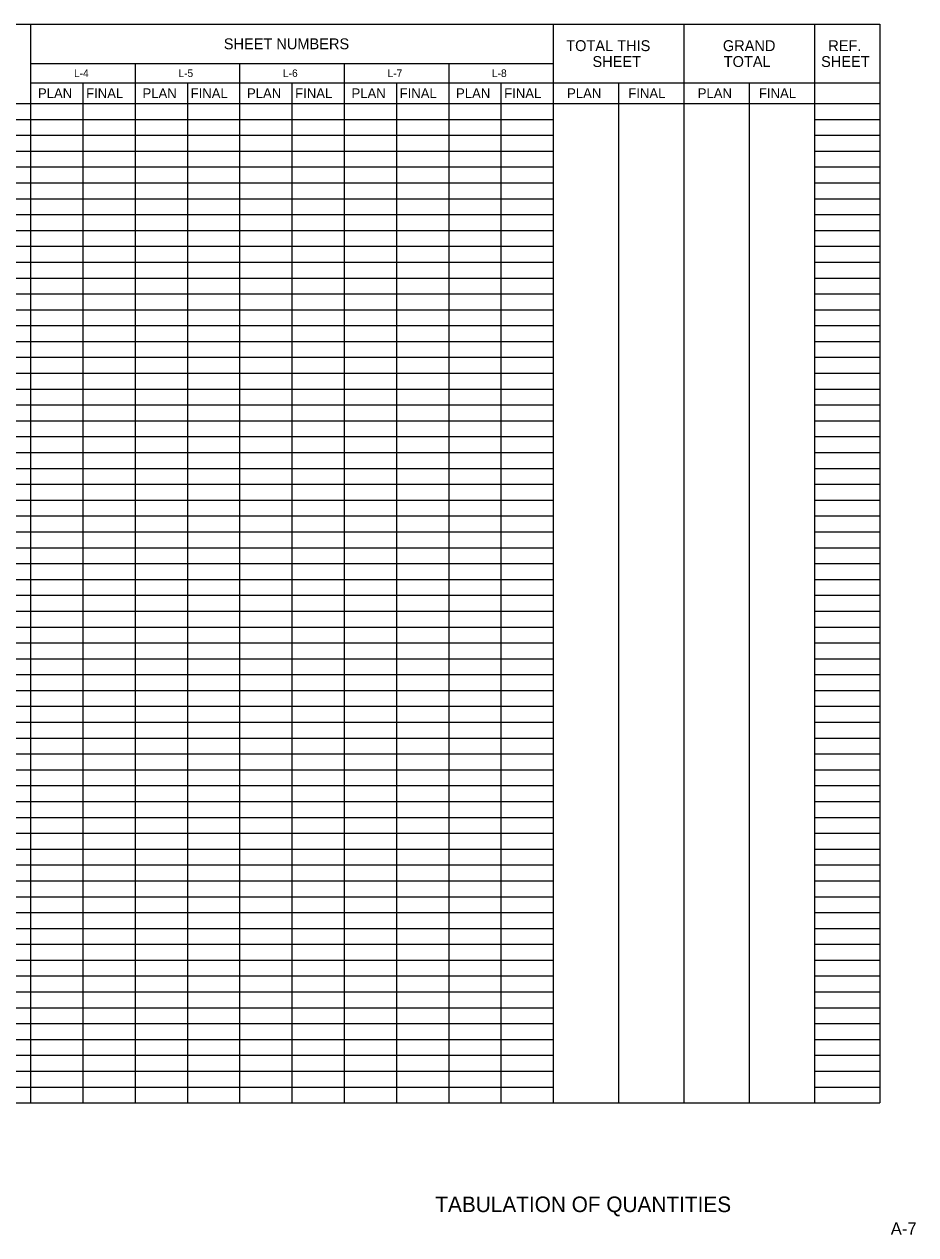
# Model space of a CAD drawing. Extents: x 56 to 1513, y -69 to 5602.
# Drawn here: x 796 to 1513, y 3444 to 4417 of the extents above; entities that cross this region are included whole.
import ezdxf

# ---------------------------------------------------------------- set-up
doc = ezdxf.new("R2010")
doc.units = 0
for name, color, linetype in [('Logo_dp', 7, 'Continuous'), ('SheetLines_dp', 7, 'Continuous'), ('TextCurveData', 7, 'Continuous'), ('TextMinor', 7, 'Continuous'), ('TextMisc', 7, 'Continuous'), ('TextNotes', 7, 'Continuous')]:
    doc.layers.add(name, color=color, linetype=linetype)

msp = doc.modelspace()

# ---------------------------------------------------------------- linework, layer by layer
at = {"layer": 'SheetLines_dp'}
for p, q in [((801.5, 4416.62), (801.5, 4369.37)), ((801.5, 4416.62), (801.5, 3549.62)), ((1221.5, 4416.62), (1221.5, 3549.62)), ((1221.5, 4416.62), (1221.5, 3549.62)), ((1326.5, 4416.62), (1326.5, 3549.62)), ((1431.5, 4416.62), (1431.5, 3549.62)), ((1484, 4416.62), (1484, 3549.62)), ((801.5, 4385.12), (1221.5, 4385.12)), ((801.5, 4385.12), (1221.5, 4385.12)), ((885.5, 4385.12), (885.5, 3549.62)), ((885.5, 4385.12), (885.5, 3549.62)), ((969.5, 4385.12), (969.5, 3549.62)), ((969.5, 4385.12), (969.5, 4369.37)), ((1053.5, 4385.12), (1053.5, 3549.62)), ((1053.5, 4385.12), (1053.5, 4369.37)), ((1137.5, 4385.12), (1137.5, 3549.62)), ((1137.5, 4385.12), (1137.5, 3549.62)), ((801.5, 4369.37), (1484, 4369.37)), ((1221.5, 4369.37), (1484, 4369.37)), ((1326.5, 4369.37), (1326.5, 3549.62)), ((56, 4352.87), (1484, 4352.87)), ((801.5, 4352.87), (801.5, 3549.62)), ((969.5, 4352.87), (969.5, 3549.62)), ((1053.5, 4352.87), (1053.5, 3549.62)), ((1221.5, 4352.87), (1431.5, 4352.87)), ((1431.5, 4352.87), (1431.5, 3549.62)), ((56, 3549.62), (1484, 3549.62))]:
    msp.add_line(p, q, dxfattribs=at)
at = {"layer": 'TextMinor'}
for q in [(1431.5, 4416.62), (1484, 4416.62)]:
    msp.add_line((56, 4416.62), q, dxfattribs=at)
at = {"layer": 'TextMisc'}
for p, q in [((843.5, 4369.37), (843.5, 3549.62)), ((843.5, 4369.37), (843.5, 3549.62)), ((927.5, 4369.37), (927.5, 3549.62)), ((927.5, 4369.37), (927.5, 3549.62)), ((969.5, 4369.37), (969.5, 4352.87)), ((1011.5, 4369.37), (1011.5, 3549.62)), ((1011.5, 4369.37), (1011.5, 3549.62)), ((1053.5, 4369.37), (1053.5, 4352.87)), ((1095.5, 4369.37), (1095.5, 3549.62)), ((1095.5, 4369.37), (1095.5, 3549.62)), ((1179.5, 4369.37), (1179.5, 3549.62)), ((1179.5, 4369.37), (1179.5, 3549.62)), ((1274, 4369.37), (1274, 3549.62)), ((1274, 4369.37), (1274, 3549.62)), ((1379, 4369.37), (1379, 3549.62)), ((1379, 4369.37), (1379, 3549.62)), ((56, 4352.87), (1221.5, 4352.87)), ((1431.5, 4352.87), (1484, 4352.87)), ((56, 4340.12), (1221.5, 4340.12)), ((56, 4340.12), (1221.5, 4340.12)), ((1431.5, 4340.12), (1484, 4340.12)), ((1431.5, 4340.12), (1484, 4340.12)), ((56, 4327.37), (1221.5, 4327.37)), ((56, 4327.37), (1221.5, 4327.37)), ((1431.5, 4327.37), (1484, 4327.37)), ((1431.5, 4327.37), (1484, 4327.37)), ((56, 4314.62), (1221.5, 4314.62)), ((56, 4314.62), (1221.5, 4314.62)), ((1431.5, 4314.62), (1484, 4314.62)), ((1431.5, 4314.62), (1484, 4314.62)), ((56, 4301.87), (1221.5, 4301.87)), ((56, 4301.87), (1221.5, 4301.87)), ((1431.5, 4301.87), (1484, 4301.87)), ((1431.5, 4301.87), (1484, 4301.87)), ((56, 4289.12), (1221.5, 4289.12)), ((56, 4289.12), (1221.5, 4289.12)), ((1431.5, 4289.12), (1484, 4289.12)), ((1431.5, 4289.12), (1484, 4289.12)), ((56, 4276.37), (1221.5, 4276.37)), ((56, 4276.37), (1221.5, 4276.37)), ((1431.5, 4276.37), (1484, 4276.37)), ((1431.5, 4276.37), (1484, 4276.37)), ((56, 4263.62), (1221.5, 4263.62)), ((56, 4263.62), (1221.5, 4263.62)), ((1431.5, 4263.62), (1484, 4263.62)), ((1431.5, 4263.62), (1484, 4263.62)), ((56, 4250.87), (1221.5, 4250.87)), ((56, 4250.87), (1221.5, 4250.87)), ((1431.5, 4250.87), (1484, 4250.87)), ((1431.5, 4250.87), (1484, 4250.87)), ((56, 4238.12), (1221.5, 4238.12)), ((56, 4238.12), (1221.5, 4238.12)), ((1431.5, 4238.12), (1484, 4238.12)), ((1431.5, 4238.12), (1484, 4238.12)), ((56, 4225.37), (1221.5, 4225.37)), ((56, 4225.37), (1221.5, 4225.37)), ((1431.5, 4225.37), (1484, 4225.37)), ((1431.5, 4225.37), (1484, 4225.37)), ((56, 4212.62), (1221.5, 4212.62)), ((56, 4212.62), (1221.5, 4212.62)), ((1431.5, 4212.62), (1484, 4212.62)), ((1431.5, 4212.62), (1484, 4212.62)), ((56, 4199.87), (1221.5, 4199.87)), ((56, 4199.87), (1221.5, 4199.87)), ((1431.5, 4199.87), (1484, 4199.87)), ((1431.5, 4199.87), (1484, 4199.87)), ((56, 4187.12), (1221.5, 4187.12)), ((56, 4187.12), (1221.5, 4187.12)), ((1431.5, 4187.12), (1484, 4187.12)), ((1431.5, 4187.12), (1484, 4187.12)), ((56, 4174.37), (1221.5, 4174.37)), ((56, 4174.37), (1221.5, 4174.37)), ((1431.5, 4174.37), (1484, 4174.37)), ((1431.5, 4174.37), (1484, 4174.37)), ((56, 4161.62), (1221.5, 4161.62)), ((56, 4161.62), (1221.5, 4161.62)), ((1431.5, 4161.62), (1484, 4161.62)), ((1431.5, 4161.62), (1484, 4161.62)), ((56, 4148.87), (1221.5, 4148.87)), ((56, 4148.87), (1221.5, 4148.87)), ((1431.5, 4148.87), (1484, 4148.87)), ((1431.5, 4148.87), (1484, 4148.87)), ((56, 4136.12), (1221.5, 4136.12)), ((56, 4136.12), (1221.5, 4136.12)), ((1431.5, 4136.12), (1484, 4136.12)), ((1431.5, 4136.12), (1484, 4136.12)), ((56, 4123.37), (1221.5, 4123.37)), ((56, 4123.37), (1221.5, 4123.37)), ((1431.5, 4123.37), (1484, 4123.37)), ((1431.5, 4123.37), (1484, 4123.37)), ((56, 4110.62), (1221.5, 4110.62)), ((56, 4110.62), (1221.5, 4110.62)), ((1431.5, 4110.62), (1484, 4110.62)), ((1431.5, 4110.62), (1484, 4110.62)), ((56, 4097.87), (1221.5, 4097.87)), ((56, 4097.87), (1221.5, 4097.87)), ((1431.5, 4097.87), (1484, 4097.87)), ((1431.5, 4097.87), (1484, 4097.87)), ((56, 4085.12), (1221.5, 4085.12)), ((56, 4085.12), (1221.5, 4085.12)), ((1431.5, 4085.12), (1484, 4085.12)), ((1431.5, 4085.12), (1484, 4085.12)), ((56, 4072.37), (1221.5, 4072.37)), ((56, 4072.37), (1221.5, 4072.37)), ((1431.5, 4072.37), (1484, 4072.37)), ((1431.5, 4072.37), (1484, 4072.37)), ((56, 4059.62), (1221.5, 4059.62)), ((56, 4059.62), (1221.5, 4059.62)), ((1431.5, 4059.62), (1484, 4059.62)), ((1431.5, 4059.62), (1484, 4059.62)), ((56, 4046.87), (1221.5, 4046.87)), ((56, 4046.87), (1221.5, 4046.87)), ((1431.5, 4046.87), (1484, 4046.87)), ((1431.5, 4046.87), (1484, 4046.87)), ((56, 4034.12), (1221.5, 4034.12)), ((56, 4034.12), (1221.5, 4034.12)), ((1431.5, 4034.12), (1484, 4034.12)), ((1431.5, 4034.12), (1484, 4034.12)), ((56, 4021.37), (1221.5, 4021.37)), ((56, 4021.37), (1221.5, 4021.37)), ((1431.5, 4021.37), (1484, 4021.37)), ((1431.5, 4021.37), (1484, 4021.37)), ((56, 4008.62), (1221.5, 4008.62)), ((56, 4008.62), (1221.5, 4008.62)), ((1431.5, 4008.62), (1484, 4008.62)), ((1431.5, 4008.62), (1484, 4008.62)), ((56, 3995.87), (1221.5, 3995.87)), ((56, 3995.87), (1221.5, 3995.87)), ((1431.5, 3995.87), (1484, 3995.87)), ((1431.5, 3995.87), (1484, 3995.87)), ((56, 3983.12), (1221.5, 3983.12)), ((56, 3983.12), (1221.5, 3983.12)), ((1431.5, 3983.12), (1484, 3983.12)), ((1431.5, 3983.12), (1484, 3983.12)), ((56, 3970.37), (1221.5, 3970.37)), ((56, 3970.37), (1221.5, 3970.37)), ((1431.5, 3970.37), (1484, 3970.37)), ((1431.5, 3970.37), (1484, 3970.37)), ((56, 3957.62), (1221.5, 3957.62)), ((56, 3957.62), (1221.5, 3957.62)), ((1431.5, 3957.62), (1484, 3957.62)), ((1431.5, 3957.62), (1484, 3957.62)), ((56, 3944.87), (1221.5, 3944.87)), ((56, 3944.87), (1221.5, 3944.87)), ((1431.5, 3944.87), (1484, 3944.87)), ((1431.5, 3944.87), (1484, 3944.87)), ((56, 3932.12), (1221.5, 3932.12)), ((56, 3932.12), (1221.5, 3932.12)), ((1431.5, 3932.12), (1484, 3932.12)), ((1431.5, 3932.12), (1484, 3932.12)), ((56, 3919.37), (1221.5, 3919.37)), ((56, 3919.37), (1221.5, 3919.37)), ((1431.5, 3919.37), (1484, 3919.37)), ((1431.5, 3919.37), (1484, 3919.37)), ((56, 3906.62), (1221.5, 3906.62)), ((56, 3906.62), (1221.5, 3906.62)), ((1431.5, 3906.62), (1484, 3906.62)), ((1431.5, 3906.62), (1484, 3906.62)), ((56, 3893.87), (1221.5, 3893.87)), ((56, 3893.87), (1221.5, 3893.87)), ((1431.5, 3893.87), (1484, 3893.87)), ((1431.5, 3893.87), (1484, 3893.87)), ((56, 3881.12), (1221.5, 3881.12)), ((56, 3881.12), (1221.5, 3881.12)), ((1431.5, 3881.12), (1484, 3881.12)), ((1431.5, 3881.12), (1484, 3881.12)), ((56, 3868.37), (1221.5, 3868.37)), ((56, 3868.37), (1221.5, 3868.37)), ((1431.5, 3868.37), (1484, 3868.37)), ((1431.5, 3868.37), (1484, 3868.37)), ((56, 3855.62), (1221.5, 3855.62)), ((56, 3855.62), (1221.5, 3855.62)), ((1431.5, 3855.62), (1484, 3855.62)), ((1431.5, 3855.62), (1484, 3855.62)), ((56, 3842.87), (1221.5, 3842.87)), ((56, 3842.87), (1221.5, 3842.87)), ((1431.5, 3842.87), (1484, 3842.87)), ((1431.5, 3842.87), (1484, 3842.87)), ((56, 3830.12), (1221.5, 3830.12)), ((56, 3830.12), (1221.5, 3830.12)), ((1431.5, 3830.12), (1484, 3830.12)), ((1431.5, 3830.12), (1484, 3830.12)), ((56, 3817.37), (1221.5, 3817.37)), ((56, 3817.37), (1221.5, 3817.37)), ((1431.5, 3817.37), (1484, 3817.37)), ((1431.5, 3817.37), (1484, 3817.37)), ((56, 3804.62), (1221.5, 3804.62)), ((56, 3804.62), (1221.5, 3804.62)), ((1431.5, 3804.62), (1484, 3804.62)), ((1431.5, 3804.62), (1484, 3804.62)), ((56, 3791.87), (1221.5, 3791.87)), ((56, 3791.87), (1221.5, 3791.87)), ((1431.5, 3791.87), (1484, 3791.87)), ((1431.5, 3791.87), (1484, 3791.87)), ((56, 3779.12), (1221.5, 3779.12)), ((56, 3779.12), (1221.5, 3779.12)), ((1431.5, 3779.12), (1484, 3779.12)), ((1431.5, 3779.12), (1484, 3779.12)), ((56, 3766.37), (1221.5, 3766.37)), ((56, 3766.37), (1221.5, 3766.37)), ((1431.5, 3766.37), (1484, 3766.37)), ((1431.5, 3766.37), (1484, 3766.37)), ((56, 3753.62), (1221.5, 3753.62)), ((56, 3753.62), (1221.5, 3753.62)), ((1431.5, 3753.62), (1484, 3753.62)), ((1431.5, 3753.62), (1484, 3753.62)), ((56, 3740.87), (1221.5, 3740.87)), ((56, 3740.87), (1221.5, 3740.87)), ((1431.5, 3740.87), (1484, 3740.87)), ((1431.5, 3740.87), (1484, 3740.87)), ((56, 3728.12), (1221.5, 3728.12)), ((56, 3728.12), (1221.5, 3728.12)), ((1431.5, 3728.12), (1484, 3728.12)), ((1431.5, 3728.12), (1484, 3728.12)), ((56, 3715.37), (1221.5, 3715.37)), ((56, 3715.37), (1221.5, 3715.37)), ((1431.5, 3715.37), (1484, 3715.37)), ((1431.5, 3715.37), (1484, 3715.37)), ((56, 3702.62), (1221.5, 3702.62)), ((56, 3702.62), (1221.5, 3702.62)), ((1431.5, 3702.62), (1484, 3702.62)), ((1431.5, 3702.62), (1484, 3702.62)), ((56, 3689.87), (1221.5, 3689.87)), ((56, 3689.87), (1221.5, 3689.87)), ((1431.5, 3689.87), (1484, 3689.87)), ((1431.5, 3689.87), (1484, 3689.87)), ((56, 3677.12), (1221.5, 3677.12)), ((56, 3677.12), (1221.5, 3677.12)), ((1431.5, 3677.12), (1484, 3677.12)), ((1431.5, 3677.12), (1484, 3677.12)), ((56, 3664.37), (1221.5, 3664.37)), ((56, 3664.37), (1221.5, 3664.37)), ((1431.5, 3664.37), (1484, 3664.37)), ((1431.5, 3664.37), (1484, 3664.37)), ((56, 3651.62), (1221.5, 3651.62)), ((56, 3651.62), (1221.5, 3651.62)), ((1431.5, 3651.62), (1484, 3651.62)), ((1431.5, 3651.62), (1484, 3651.62)), ((56, 3638.87), (1221.5, 3638.87)), ((56, 3638.87), (1221.5, 3638.87)), ((1431.5, 3638.87), (1484, 3638.87)), ((1431.5, 3638.87), (1484, 3638.87)), ((56, 3626.12), (1221.5, 3626.12)), ((56, 3626.12), (1221.5, 3626.12)), ((1431.5, 3626.12), (1484, 3626.12)), ((1431.5, 3626.12), (1484, 3626.12)), ((56, 3613.37), (1221.5, 3613.37)), ((56, 3613.37), (1221.5, 3613.37)), ((1431.5, 3613.37), (1484, 3613.37)), ((1431.5, 3613.37), (1484, 3613.37)), ((56, 3600.62), (1221.5, 3600.62)), ((56, 3600.62), (1221.5, 3600.62)), ((1431.5, 3600.62), (1484, 3600.62)), ((1431.5, 3600.62), (1484, 3600.62)), ((56, 3587.87), (1221.5, 3587.87)), ((56, 3587.87), (1221.5, 3587.87)), ((1431.5, 3587.87), (1484, 3587.87)), ((1431.5, 3587.87), (1484, 3587.87)), ((56, 3575.12), (1221.5, 3575.12)), ((56, 3575.12), (1221.5, 3575.12)), ((1431.5, 3575.12), (1484, 3575.12)), ((1431.5, 3575.12), (1484, 3575.12)), ((56, 3562.37), (1221.5, 3562.37)), ((56, 3562.37), (1221.5, 3562.37)), ((1431.5, 3562.37), (1484, 3562.37)), ((1431.5, 3562.37), (1484, 3562.37))]:
    msp.add_line(p, q, dxfattribs=at)

# ---------------------------------------------------------------- texts
at = {"layer": 'Logo_dp'}
msp.add_text('A-7', height=10, dxfattribs=at).set_placement((1492.76, 3443.6))
at = {"layer": 'TextCurveData'}
for s, height, p in [('SHEET NUMBERS', 8.75, (956.75, 4396.49)), ('TOTAL THIS', 8.75, (1231.95, 4394.99)), ('GRAND', 8.75, (1357.86, 4394.99)), ('REF.', 8.75, (1442.56, 4394.99)), ('SHEET', 8.75, (1253.05, 4382.24)), ('TOTAL', 8.75, (1358.54, 4382.24)), ('SHEET', 8.75, (1436.8, 4382.24)), ('L-4', 6.125, (836.37, 4374.18)), ('L-5', 6.125, (920.27, 4374.18)), ('L-6', 6.125, (1004.31, 4374.18)), ('L-7', 6.125, (1088.38, 4374.18)), ('L-8', 6.125, (1172.26, 4374.18)), ('PLAN', 7.875, (807.4, 4357.18)), ('FINAL', 7.875, (846.09, 4357.18)), ('PLAN', 7.875, (891.4, 4357.18)), ('FINAL', 7.875, (930.09, 4357.18)), ('PLAN', 7.875, (975.4, 4357.18)), ('FINAL', 7.875, (1014.09, 4357.18)), ('PLAN', 7.875, (1059.4, 4357.18)), ('FINAL', 7.875, (1098.09, 4357.18)), ('PLAN', 7.875, (1143.4, 4357.18)), ('FINAL', 7.875, (1182.09, 4357.18)), ('PLAN', 7.875, (1232.65, 4357.18)), ('FINAL', 7.875, (1281.84, 4357.18)), ('PLAN', 7.875, (1337.65, 4357.18)), ('FINAL', 7.875, (1386.84, 4357.18))]:
    msp.add_text(s, height=height, dxfattribs=at).set_placement(p)
at = {"layer": 'TextNotes'}
msp.add_text('TABULATION OF QUANTITIES ', height=12.5, dxfattribs=at).set_placement((1126.74, 3461.84))

doc.saveas('drawing.dxf')
